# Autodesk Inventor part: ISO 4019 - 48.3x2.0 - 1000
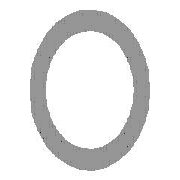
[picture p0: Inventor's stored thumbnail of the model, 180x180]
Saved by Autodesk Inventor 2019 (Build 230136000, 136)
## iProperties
_CCFamilyMember: 14
_CCFamilyDisplayName: ISO 4019 (Profils creux circulaires - Formés à froid) - Aciers de construction - Coupes creuses profilées formées à froid, soudées — ISO 4019 (Profils creux cir
_FrameMemberDoc: Frame Member File
_Version: 15.0.0
_GetPNFromCC: 1
Created: 2018-01
Part Number: ISO 4019 - 48.3x2.0 - 1000
Material: Acier, doux
Description: Aciers de construction - Coupes creuses profilées formées à froid, soudées
Document SubType Name: Modeling
Standard: ISO
Designer: Fabian Perrée
Standard Revision: Second edition 2001-09-01
Standards Organization: ISO
Language: fr-FR
Size Designation: 48.3x2.0
Categories: <MemberInstance><Categories><Category DisplayName="Profilés" InternalName="089c4875-fa83-4c05-b084-43b9cc11f5ed" Mnemonic="GRDR"><CategoryParameter DisplayName=
Stock Number: 48.3x2.0
Density: 7.85 g/cm^3
Appearance: Semi-poli
Mass: 2169.28 g
Surface Area: 2784.05 cm^2
Volume: 276.341 cm^3
IsCustomPart: 1
G_L: 1000,000 mm
G_W: 48,300 mm
G_H: 48,300 mm
+B165CBF4-667B-4DA3-AF45-A5B7E1368CCB+DETAILDECOUPE1: Grugeage
+8F40B860-9FE4-4B34-9FFF-D4066A5AD6B0+DETAILDECOUPE2: Grugeage
Author: Fabian Perrée
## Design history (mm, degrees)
node "Plan de départ"
node "Plan de fin"
sketch "Esquisse"
  geometry: C1 r 22.15 at (0, 0); C2 r 24.15 at (0, 0); 2 further points
  constraints: 3 coincident, 2 centre point
  dimensions: "d0" = 48.3 diameter of C2 (= G_H); "d1" = 2 radial gap between concentric circles of C2 C1 (= G_T)
extrude "Corps" new body sketch "Esquisse" stored distance "d2" = 1000 (= G_L); taper "d3" = 0 deg
node "Driven Length"
  sketch "Sketch3"
    geometry: L1 (0, 0)-(10, 0) reference
    constraints: 2 end point, 1 horizontal
  workplane "Work Plane3"
  sketch "Sketch4"
    geometry: L1 (-2, 0)-(12, 0) reference; L2 (-2, 1000)-(12, 1000) reference
    dimensions: "d7" = 1000 distance between parallel lines of L1 L2 (derived)
body "Solid1"
feature "Sculpter1"
feature "Combiner1"
feature "Sculpter3"
feature "Combiner3"
body "Srf26"
body "Srf27"
node "Solide10"
body "Srf29"
body "Srf30"
node "Solide11"
feature "Surface1"
body "Srf25"
feature "Carreau délimité17" dims "d40" = 5, "d41" = 0
feature "Carreau délimité18" dims "d42" = 5, "d43" = 0
feature "Surface3"
body "Srf28"
feature "Carreau délimité19" dims "d44" = 5, "d45" = 0
feature "Carreau délimité20" dims "d46" = 5, "d47" = 0
other parameters: "G_H" = 48.3 [user parameter; used in 1 equation term], "G_T" = 2 [user parameter; used in 1 equation term], "G_L" = 1000 (= d7) [user parameter; used in 1 equation term], "G_OFFSET_START" = 0 [user parameter; used in 1 equation term], "G_OFFSET_END" = 0 [user parameter; used in 1 equation term], "d4" = 0 (computed from G_OFFSET_START), "d6" = 90 deg, "MAS" = 0.228 [user parameter]
